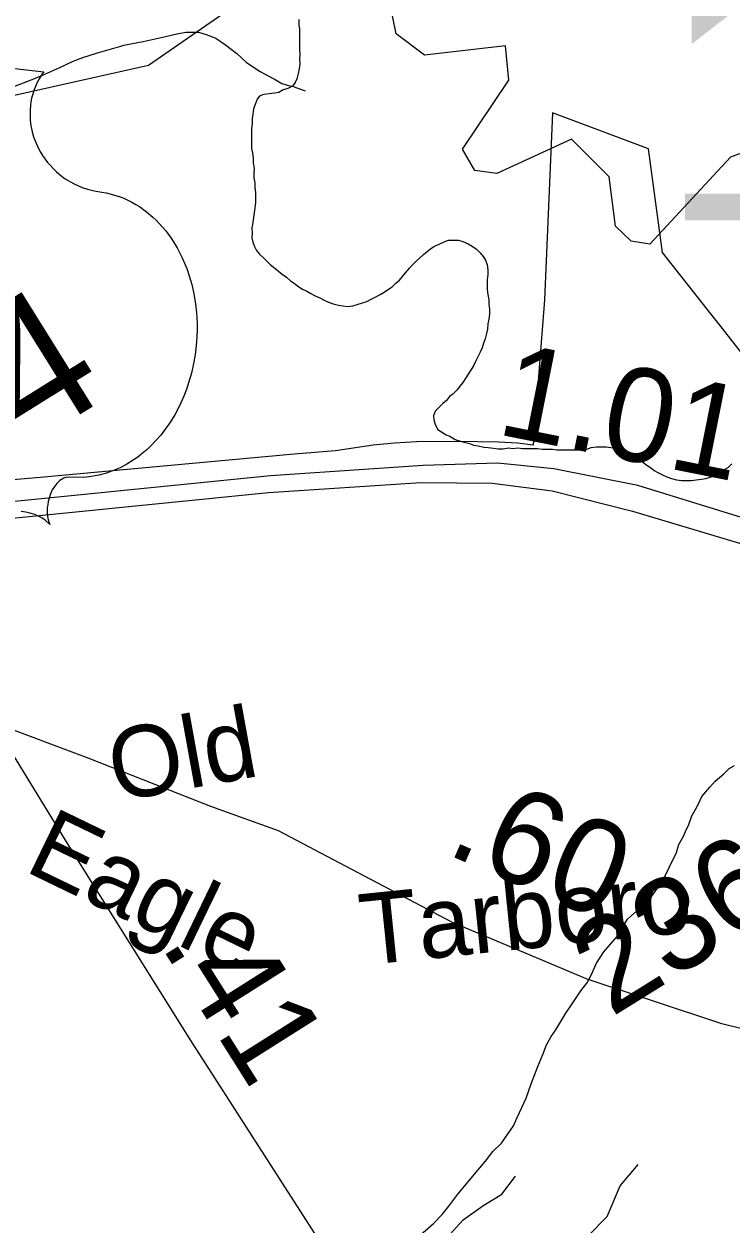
# Model space of a CAD drawing. Extents: x 2001466 to 31450019, y -30647475 to 847247.
# Drawn here: x 2173495 to 2175385, y 745745 to 748952 of the extents above; entities that cross this region are included whole.
import ezdxf

# ---------------------------------------------------------------- set-up
doc = ezdxf.new("R2010")
doc.units = 0
for name, color, linetype in [('Exist Boundary Political City Limit New', 7, 'Continuous'), ('Exist Hydrographic Creek Single Shore', 7, 'Continuous'), ('Exist Hydrographic Misc Water Feature', 7, 'Continuous'), ('Exist Road Non-System Type 51', 7, 'Continuous'), ('Exist Road Primary US Divided Attributed', 7, 'Continuous'), ('Exist Road Primary US Mileage Hundredths English Label', 7, 'Continuous'), ('Exist Road Primary US Shield CELL', 7, 'Continuous'), ('Exist Road Primary US Shield Number Label', 7, 'Continuous'), ('Exist Road Secondary Mileage Hundredths English Label', 7, 'Continuous'), ('Exist Road Secondary Structure Standard Bridge Number Label', 7, 'Continuous'), ('Exist Road Secondary Type 41 Attributed', 7, 'Continuous'), ('Exist Road Secondary Type 51 Attributed', 7, 'Continuous'), ('Exist Road Secondary Type 51 Label', 7, 'Continuous'), ('Exist Road Secondary Type 51 Number Label', 7, 'Continuous'), ('Map Preparation Boundary City Limit Buffer Line', 7, 'Continuous')]:
    doc.layers.add(name, color=color, linetype=linetype)

msp = doc.modelspace()

# ---------------------------------------------------------------- linework, layer by layer
at = {"layer": 'Exist Boundary Political City Limit New'}
for points in [[(2173301, 748723.8), (2173827.2, 748841.9), (2174050.2, 748995.6)], [(2175423, 748060.1), (2175351.8, 748150.6), (2175330.8, 748177.1), (2175201.8, 748341.4), (2175164.2, 748617.8), (2174907.5, 748714.6), (2174886, 748214.6), (2174856, 747826.6), (2174814, 747831.3), (2174763.8, 747834.3), (2174651, 747836.3), (2174543.8, 747834.8), (2174485, 747831.6), (2174428, 747826.3), (2174327.2, 747811.5), (2174216.8, 747802.1), (2173538.2, 747739.9), (2173277.2, 747717.9)]]:
    msp.add_lwpolyline(points, dxfattribs=at)
at = {"layer": 'Exist Hydrographic Creek Single Shore'}
msp.add_lwpolyline([(2175450, 748620.4), (2175383, 748595.5), (2175168.1, 748363.7), (2175118.1, 748371.3), (2175076, 748411.5), (2175059, 748543.1), (2174958.1, 748643.6), (2174759, 748552.5), (2174700, 748560.3), (2174667.2, 748616.8), (2174791, 748801.2), (2174782, 748893.2), (2174565, 748868.2), (2174490, 748925.5), (2174473, 749007.8)], dxfattribs=at)
at = {"layer": 'Exist Hydrographic Misc Water Feature'}
for points in [[(2174229.2, 748963.3), (2174229.4, 748949.1), (2174231.2, 748937.5), (2174231, 748923.3), (2174231.2, 748909.5), (2174231.2, 748897.3), (2174231.2, 748883.5), (2174231.6, 748871.3), (2174231.4, 748857.5), (2174231.6, 748845.3), (2174229.8, 748831.4), (2174227.7, 748819.1), (2174223.6, 748805.1), (2174219.9, 748795.2), (2174212.4, 748785.4)], [(2173458.4, 748780.8), (2173516.2, 748803.4), (2173542, 748813.7), (2173590, 748835.6), (2173625.9, 748852.1), (2173651.7, 748862), (2173691.5, 748874.2), (2173753.6, 748892.4), (2173761.6, 748894.9), (2173813.1, 748904.9), (2173861.1, 748915.1), (2173903.3, 748925.4), (2173927.3, 748929.5), (2173943.5, 748929.5), (2173961.4, 748930), (2173981.3, 748923.7), (2174007.1, 748914.1), (2174033.5, 748896.3), (2174063.5, 748872.4), (2174089.3, 748848.6), (2174125.8, 748824.8), (2174147.6, 748813), (2174165.8, 748802.9), (2174183.8, 748792.9), (2174201.9, 748787.3), (2174212.4, 748785.4)], [(2174212.4, 748785.4), (2174200.3, 748779.1), (2174187.9, 748775.3), (2174175.9, 748769), (2174164.2, 748767.1), (2174150.2, 748764.8), (2174136.3, 748762.8), (2174132, 748762.6), (2174124, 748758.6), (2174118, 748750.9), (2174112.3, 748736.8), (2174108.2, 748724.8), (2174106.3, 748710.5), (2174104.3, 748698.7), (2174104.5, 748684.8), (2174102.4, 748672.5), (2174102.9, 748658.7), (2174102.9, 748644.5), (2174102.6, 748632.8), (2174102.9, 748618.6), (2174105.1, 748606.9), (2174107.2, 748592.8), (2174107.2, 748580.6), (2174109.6, 748566.8), (2174109.4, 748552.7), (2174109.4, 748540.9), (2174111.5, 748526.8), (2174111.5, 748514.6), (2174113.5, 748501), (2174113.5, 748488.8), (2174113.7, 748474.9), (2174111.9, 748460.6), (2174110, 748446.7), (2174108, 748434.8), (2174106.1, 748420.9), (2174104.1, 748406.6), (2174104.3, 748392.8), (2174104.1, 748380.6), (2174106.3, 748369), (2174110.2, 748358.6), (2174116.6, 748346.7), (2174124.4, 748337), (2174134.6, 748327), (2174142.6, 748318.9), (2174152.5, 748309.2), (2174165, 748299.3), (2174175, 748291.2), (2174184.7, 748283.3), (2174196.6, 748275.4), (2174206.8, 748265.3), (2174216.9, 748259.4), (2174227.1, 748251.4), (2174238.8, 748243.5), (2174251.1, 748237.6), (2174261.2, 748231.6), (2174272.8, 748225.7), (2174285.1, 748219.8), (2174296.8, 748214), (2174309.1, 748208.1), (2174321, 748203.8), (2174335.4, 748200.1), (2174347.5, 748198.2), (2174359.4, 748196.5), (2174373.3, 748198.4), (2174385, 748202.3), (2174399.4, 748206.6), (2174411, 748210.5), (2174423.1, 748216.4), (2174435.2, 748222.7), (2174447.1, 748228.6), (2174457.2, 748234.8), (2174468.7, 748242.8), (2174478.7, 748249), (2174488.8, 748258.8), (2174498.6, 748267), (2174506.8, 748277.2), (2174514.8, 748286.9), (2174524.9, 748299.2), (2174532.6, 748307.4), (2174542.3, 748317.3), (2174552.1, 748325.5), (2174562.4, 748335.3), (2174572.2, 748343.6), (2174582.5, 748351.4), (2174592.3, 748357.6), (2174604.4, 748363.5), (2174618.1, 748369.5), (2174629.8, 748373.8), (2174642.3, 748373.9), (2174656.3, 748373.9), (2174668, 748370.1), (2174682.3, 748364.2), (2174692.4, 748358.2), (2174704.3, 748350.4), (2174714.3, 748340.3), (2174722.5, 748330.2), (2174728.1, 748320.4), (2174732.6, 748308.4), (2174734.8, 748294.3), (2174734.6, 748282.5)], [(2174212.4, 748785.4), (2174223.8, 748781.2), (2174246, 748773.4)], [(2174734.6, 748282.5), (2174732.6, 748268.2), (2174732.8, 748254.4), (2174733, 748242.2), (2174734.8, 748228.5), (2174737.3, 748214.4), (2174736.9, 748202.7), (2174739.3, 748188.5), (2174739.3, 748176.3), (2174737.1, 748162.5), (2174735, 748150.6), (2174733.6, 748136.2), (2174731.5, 748124.4), (2174727.6, 748110.4), (2174723.3, 748098.4), (2174719.6, 748086.4), (2174713.9, 748074.3), (2174707.6, 748062.2), (2174701.8, 748050.1), (2174696.1, 748038.5), (2174690.1, 748028.4), (2174682.1, 748016.2), (2174675.8, 748006.2), (2174668.2, 747994), (2174660.2, 747984.2), (2174652.6, 747974), (2174642.3, 747963.8), (2174632.5, 747956), (2174624.5, 747945.8), (2174614.3, 747938), (2174604.4, 747927.8), (2174594.8, 747917.9), (2174589, 747905.8), (2174590.7, 747893.7), (2174594.8, 747879.7), (2174601.3, 747867.8), (2174611, 747861.9), (2174623.3, 747854), (2174633.1, 747850), (2174647.1, 747841.8), (2174658.7, 747838), (2174670.8, 747834.2), (2174685.2, 747830.4), (2174697.3, 747826.1), (2174709.2, 747824.3), (2174723.5, 747820.5), (2174735.4, 747820.4), (2174749.6, 747818.6), (2174761.1, 747816.8), (2174775.2, 747816.8), (2174789.6, 747818.7), (2174801.1, 747816.9), (2174815, 747818.8), (2174827.5, 747817), (2174841, 747817), (2174855.2, 747817.3), (2174867.1, 747817.1), (2174881.2, 747815.4), (2174893.1, 747815.6), (2174907.1, 747815.5), (2174919.2, 747813.7), (2174933.1, 747813.6), (2174945, 747813.8), (2174959.2, 747813.7), (2174973.1, 747814), (2174985, 747813.9), (2174998.9, 747815.8), (2175011, 747820), (2175025, 747822), (2175037.1, 747822.2), (2175051, 747822.1), (2175063.1, 747820.3), (2175075, 747818.5), (2175088.9, 747812.3), (2175101, 747806.4), (2175113.1, 747802.6), (2175125, 747794.7), (2175135.1, 747788.8), (2175147.4, 747782.9), (2175157, 747774.9), (2175169.3, 747766.9), (2175179.4, 747758.9), (2175189, 747753), (2175201.7, 747747), (2175213.4, 747741.2), (2175225.5, 747737.3), (2175239.3, 747733.2), (2175253.4, 747731.5), (2175265.5, 747731.7), (2175279.4, 747731.6), (2175291.7, 747733.9), (2175305.7, 747735.8), (2175317.4, 747737.6), (2175331.7, 747742), (2175343, 747746), (2175355.5, 747752.2), (2175365.4, 747760), (2175377.5, 747766.3), (2175387.1, 747776.2)], [(2174547.2, 745710.2), (2174589, 745746.5), (2174612.8, 745770.5), (2174630.7, 745792.6), (2174654.6, 745824.6), (2174678, 745852.7), (2174708, 745889.2), (2174728.1, 745912.9), (2174747.7, 745939.1), (2174771.3, 745961.5), (2174803.3, 746007.4), (2174813.2, 746029.4), (2174837.3, 746081.7), (2174850.9, 746119.9), (2174868.7, 746165.9), (2174882.1, 746197.9), (2174891.9, 746224), (2174904.2, 746246.1), (2174916.1, 746264.1), (2174943.4, 746308.3), (2174961.6, 746336.4), (2174983.1, 746368.4), (2174999.1, 746388.3), (2175011, 746410.4), (2175024.8, 746442.4), (2175044.7, 746472.7), (2175080.7, 746513.1), (2175108, 746559.3), (2175166, 746611.3), (2175201.5, 746661.5), (2175238.8, 746737.8), (2175245, 746759.6), (2175256.9, 746779.7), (2175266.5, 746801.8), (2175270.8, 746809.7), (2175280.3, 746835.8), (2175290.5, 746854.1), (2175298.3, 746870), (2175306.3, 746887.9), (2175327.8, 746912.2), (2175342, 746928.3), (2175365.8, 746948.2), (2175379.5, 746962.4), (2175393.7, 746970.4)]]:
    msp.add_lwpolyline(points, dxfattribs=at)
at = {"layer": 'Exist Road Non-System Type 51'}
for points in [[(2174815.7, 745607.9), (2174841.2, 745638.9), (2174905.3, 745661.8), (2174955.6, 745677.9), (2175001.4, 745712.2), (2175054, 745764.8), (2175088.3, 745847.2), (2175136.4, 745904.5)], [(2174552.8, 745599.7), (2174588.7, 745653.6), (2174625.3, 745708.6), (2174668.8, 745756.6), (2174721.4, 745793.3), (2174771.8, 745825.3), (2174808.4, 745873.4)]]:
    msp.add_lwpolyline(points, dxfattribs=at)
at = {"layer": 'Exist Road Primary US Divided Attributed'}
for points in [[(2175518.5, 747598.2), (2175424, 747629.7), (2175135.9, 747718.5), (2174911.5, 747763.3), (2174760.6, 747778.2), (2174562, 747771.8), (2174153.2, 747744.5), (2173272.9, 747656.5), (2173021.7, 747633.7), (2172877.1, 747646.1), (2172656.3, 747662.8), (2172147.2, 747746.8)], [(2172172.8, 747697.5), (2172641.7, 747618.1), (2172864.6, 747601.3), (2173012.9, 747588.6), (2173268.2, 747611.8), (2174148, 747699.7), (2174555.3, 747726.9), (2174746.6, 747724.3), (2174906.4, 747703.8), (2175121.3, 747649.5), (2175398.3, 747566.7), (2175505.3, 747535.1)]]:
    msp.add_lwpolyline(points, dxfattribs=at)
at = {"layer": 'Exist Road Primary US Shield CELL'}
msp.add_lwpolyline([(2173220.5, 748861.3), (2173547.2, 748823.4), (2173543.3, 748818.2), (2173535, 748805), (2173529.1, 748793.6), (2173520.6, 748773.7), (2173517.8, 748763.8), (2173515.1, 748753.8), (2173513.2, 748743.6), (2173511.8, 748734.3), (2173510.9, 748721.6), (2173510.7, 748709.3), (2173511.2, 748696.2), (2173512.3, 748685.2), (2173516.6, 748663.5), (2173520.3, 748650.4), (2173524.1, 748639.7), (2173533.6, 748618.6), (2173538.8, 748608.9), (2173544.5, 748599.8), (2173551, 748590.4), (2173557.7, 748581.7), (2173565.4, 748573.1), (2173572.2, 748565.5), (2173581.5, 748556.8), (2173592.9, 748547.1), (2173605, 748538.3), (2173626.8, 748525.5), (2173651.6, 748514.2), (2173667.5, 748509.1), (2173682.4, 748505.4), (2173702.9, 748502.4), (2173714.2, 748500.5), (2173727.8, 748497.3), (2173751.4, 748490), (2173761.6, 748486), (2173772.4, 748481.1), (2173782.9, 748475.6), (2173793.9, 748469.6), (2173803.1, 748464), (2173822.4, 748450.1), (2173839.3, 748435.4), (2173847.8, 748427.5), (2173865.2, 748408.6), (2173873.4, 748399), (2173888.1, 748379.1), (2173903.9, 748353.9), (2173916.9, 748328.7), (2173929.8, 748297.9), (2173936.5, 748278.8), (2173942.9, 748255.7), (2173947.9, 748235.4), (2173953.4, 748204.2), (2173955.8, 748180.7), (2173957.5, 748152.4), (2173957.6, 748134.7), (2173957, 748115.3), (2173955.3, 748092.4), (2173952.4, 748067.3), (2173947.2, 748039.6), (2173942.3, 748018.5), (2173934.8, 747992.6), (2173929.8, 747977.7), (2173922, 747957.5), (2173910.3, 747931.5), (2173897.5, 747907.7), (2173886, 747888.5), (2173875.1, 747872.7), (2173860.3, 747853.3), (2173833.7, 747824.4), (2173823.5, 747814.6), (2173810.8, 747803.9), (2173798.6, 747794.5), (2173786.4, 747785.8), (2173769.4, 747775.2), (2173751.7, 747766), (2173734.3, 747758.4), (2173715.5, 747751.5), (2173694.9, 747745.8), (2173675.2, 747742.2), (2173654.3, 747740.1), (2173616.7, 747740.3), (2173606.3, 747739.5), (2173601.2, 747738), (2173590.5, 747732), (2173582, 747723.8), (2173574.4, 747713.5), (2173570.3, 747706.5), (2173565.6, 747696.2), (2173562.4, 747687.5), (2173559.4, 747675.7), (2173557.9, 747666.6), (2173556.9, 747659.5), (2173556.8, 747642.8), (2173557.6, 747635.4), (2173559.3, 747626.3), (2173563.6, 747613.9), (2173551.6, 747625.4), (2173542, 747632), (2173532.5, 747636.8), (2173523.4, 747640.6), (2173510.4, 747644.7), (2173499.4, 747647), (2173487, 747648.6)], dxfattribs=at)
at = {"layer": 'Exist Road Secondary Type 41 Attributed'}
msp.add_lwpolyline([(2176416.8, 746140), (2176329.9, 746154.6), (2176083, 746175.6), (2175666.5, 746215.4), (2175520, 746240.5), (2175359.9, 746280.3), (2174999.9, 746399.7), (2174640, 746550.4), (2174321.9, 746718), (2174175.4, 746795.5), (2173994.4, 746860.4), (2173665.8, 746990.2), (2173411, 747085.5)], dxfattribs=at)
at = {"layer": 'Exist Road Secondary Type 51 Attributed'}
msp.add_lwpolyline([(2173411, 747085.5), (2173611.9, 746758.8), (2173939.4, 746235.3), (2174548.4, 745288.7), (2174592.5, 745219.1)], dxfattribs=at)
at = {"layer": 'Map Preparation Boundary City Limit Buffer Line'}
for points in [[(2173301, 748723.8), (2173827.2, 748841.9), (2174050.2, 748995.6)], [(2175423, 748060.1), (2175351.8, 748150.6), (2175330.8, 748177.1), (2175201.8, 748341.4), (2175164.2, 748617.8), (2174907.5, 748714.6), (2174886, 748214.6), (2174856, 747826.6), (2174814, 747831.3), (2174763.8, 747834.3), (2174651, 747836.3), (2174543.8, 747834.8), (2174485, 747831.6), (2174428, 747826.3), (2174327.2, 747811.5), (2174216.8, 747802.1), (2173538.2, 747739.9), (2173277.2, 747717.9)]]:
    msp.add_lwpolyline(points, dxfattribs=at)

# ---------------------------------------------------------------- texts
at = {"layer": 'Exist Road Primary US Mileage Hundredths English Label'}
msp.add_text('1.01', height=250, rotation=348.715, dxfattribs=at).set_placement((2174753.5, 747856.8))
at = {"layer": 'Exist Road Primary US Shield Number Label'}
msp.add_text('264', height=360, rotation=31.918, dxfattribs=at).set_placement((2173048.3, 747536.8))
at = {"layer": 'Exist Road Secondary Mileage Hundredths English Label'}
for s, rotation, p in [('.60', 336.5939, (2174617.3, 746736.6)), ('.41', 302.2879, (2173857, 746492))]:
    msp.add_text(s, height=250, rotation=rotation, dxfattribs=at).set_placement(p)
at = {"layer": 'Exist Road Secondary Structure Standard Bridge Number Label'}
msp.add_text('182', height=656.17, dxfattribs=at).set_placement((2175194.8, 748427.3))
at = {"layer": 'Exist Road Secondary Type 51 Label'}
for s, rotation, p in [('Old', 10.2885, (2173739.5, 746872.6)), ('Eagle', 334.206, (2173491.7, 746690.2)), ('Tarboro', 5.8281, (2174401.7, 746436.3))]:
    msp.add_text(s, height=190, rotation=rotation, dxfattribs=at).set_placement(p)
at = {"layer": 'Exist Road Secondary Type 51 Number Label'}
msp.add_text('2365', height=250, rotation=31.918, dxfattribs=at).set_placement((2175064.1, 746296.1))

doc.saveas('drawing.dxf')
